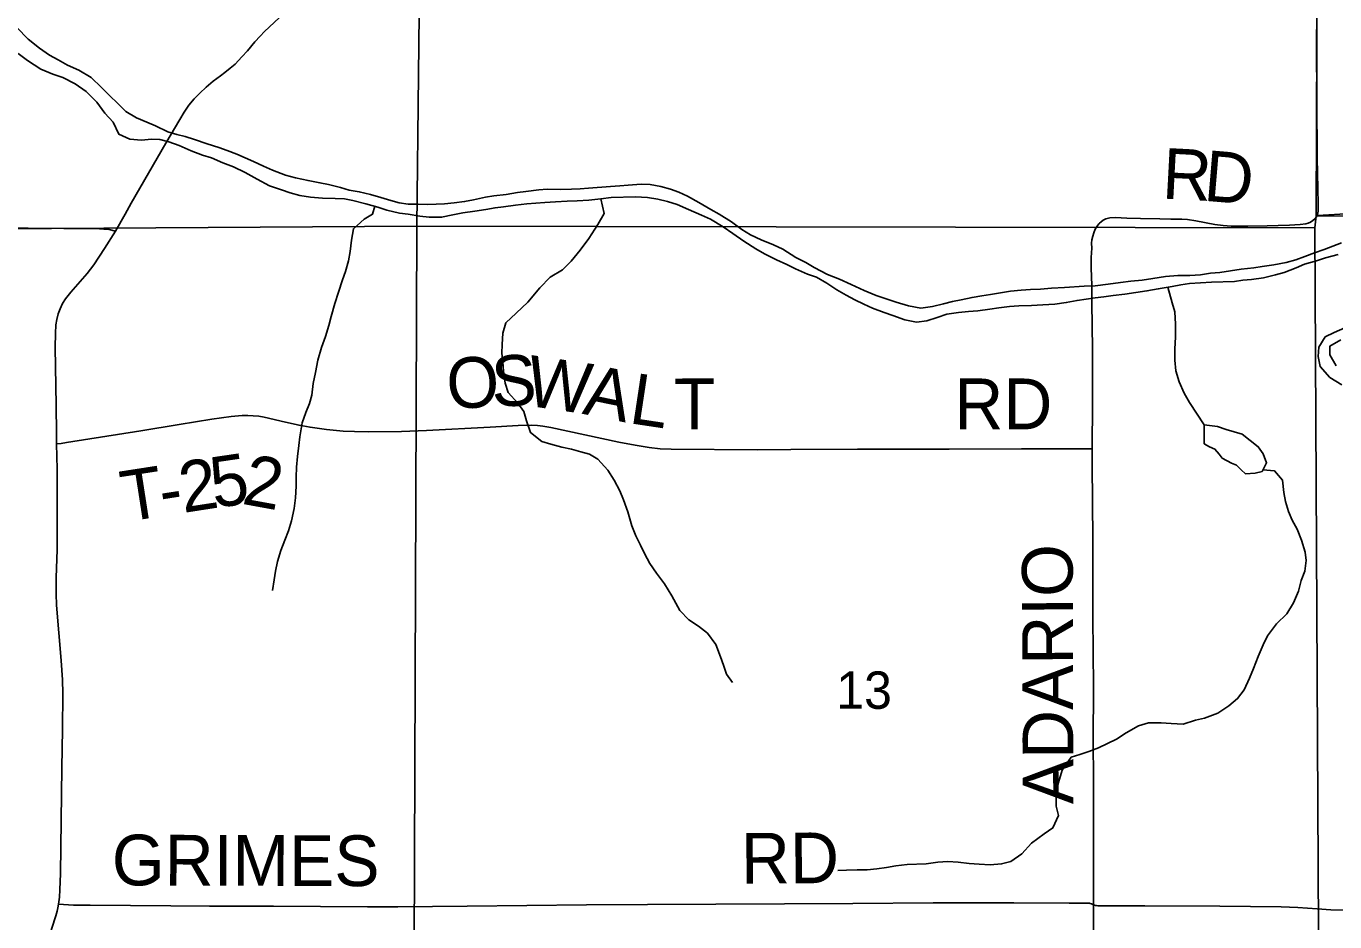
# Model space of a CAD drawing. Extents: x 0 to 34, y 0 to 22.
# Drawn here: x 3.99 to 5.455, y 15.494 to 16.497 of the extents above; entities that cross this region are included whole.
import ezdxf

# ---------------------------------------------------------------- set-up
doc = ezdxf.new("R2010")
doc.units = 0
for name, color, linetype in [('GM_X_County_Road', 7, 'Continuous'), ('GM_X_Major_River', 7, 'Continuous'), ('GM_X_Minor_Lake', 7, 'Continuous'), ('GM_X_Minor_River', 7, 'Continuous'), ('GM_X_Section', 7, 'Continuous'), ('GM_X_Section_Text', 7, 'Continuous'), ('GM_X_Township_Road', 7, 'Continuous'), ('GM_X_Township_Road_Text', 7, 'Continuous')]:
    doc.layers.add(name, color=color, linetype=linetype)

msp = doc.modelspace()

# ---------------------------------------------------------------- linework, layer by layer
at = {"layer": 'GM_X_County_Road'}
msp.add_line((4.0899, 16.2671), (4.1007, 16.2863), dxfattribs=at)
for points in [[(4.2123, 16.4449), (4.2184, 16.4497), (4.2239, 16.4544), (4.2313, 16.4623), (4.2376, 16.4693), (4.2459, 16.4793), (4.2518, 16.4857), (4.2568, 16.4907), (4.2788, 16.5115)], [(4.1007, 16.2863), (4.1075, 16.2985), (4.1463, 16.3659), (4.1621, 16.3924), (4.1669, 16.4006), (4.1722, 16.4083), (4.1782, 16.4154), (4.1845, 16.4219), (4.1914, 16.4286), (4.1992, 16.4352), (4.2076, 16.4412), (4.2123, 16.4449)], [(4.024, 16.0289), (4.0238, 16.0409), (4.0235, 16.072), (4.0225, 16.1372), (4.0227, 16.1528), (4.0233, 16.1622), (4.0243, 16.1684), (4.0258, 16.1745), (4.0279, 16.1804), (4.0307, 16.1861), (4.0341, 16.1914), (4.0398, 16.1988), (4.0583, 16.2199), (4.0657, 16.2297), (4.0778, 16.2477), (4.0899, 16.2671)], [(4.0262, 15.5135), (4.0272, 15.5213), (4.0277, 15.5296), (4.0283, 15.548), (4.0298, 15.6661), (4.0308, 15.7092), (4.0311, 15.7494), (4.0307, 15.7649), (4.0291, 15.7865), (4.024, 15.8485), (4.0235, 15.8609), (4.0237, 15.8795), (4.0246, 15.9105), (4.0248, 15.9415), (4.0245, 16.0005), (4.024, 16.0289)], [(4.0146, 15.4558), (4.0141, 15.4589), (4.0139, 15.462), (4.0139, 15.4652), (4.0141, 15.4684), (4.0145, 15.4715), (4.0159, 15.4777), (4.0187, 15.4867), (4.0233, 15.5003), (4.0246, 15.5056), (4.0255, 15.5094), (4.0262, 15.5135)]]:
    msp.add_lwpolyline(points, dxfattribs=at)
at = {"layer": 'GM_X_Major_River'}
for points in [[(4.1017, 16.4011), (4.0742, 16.428), (4.0629, 16.4395), (4.0489, 16.4475), (4.0364, 16.4533), (4.0258, 16.459), (4.0159, 16.4644), (4.005, 16.472), (3.9921, 16.4823), (3.9797, 16.4953)], [(3.9811, 16.4661), (3.9913, 16.4584), (4.0064, 16.4485), (4.02, 16.4431), (4.031, 16.4392), (4.045, 16.4323), (4.0571, 16.4236), (4.0692, 16.4117), (4.0782, 16.3992)], [(4.0782, 16.3992), (4.0873, 16.3894), (4.0938, 16.3757), (4.1059, 16.3704), (4.1192, 16.3693), (4.1302, 16.3704), (4.1396, 16.3697), (4.1495, 16.3674), (4.1612, 16.3632), (4.1745, 16.3571), (4.1874, 16.3522), (4.1976, 16.3492), (4.2101, 16.3439), (4.2219, 16.3393), (4.2351, 16.3329), (4.2484, 16.3253), (4.2624, 16.3181), (4.2757, 16.3135), (4.2855, 16.3101), (4.2962, 16.3071), (4.3083, 16.3052), (4.3219, 16.3041), (4.336, 16.3037), (4.3462, 16.3033), (4.3557, 16.3014), (4.3701, 16.298), (4.3837, 16.2942), (4.3939, 16.2908), (4.408, 16.2874), (4.4175, 16.2863), (4.4307, 16.284), (4.4413, 16.2828), (4.455, 16.2828), (4.4675, 16.2855), (4.4789, 16.2878), (4.4921, 16.2897), (4.5046, 16.2916), (4.5149, 16.2935), (4.5244, 16.2946), (4.5376, 16.2965), (4.5505, 16.298), (4.5604, 16.2984), (4.5706, 16.2992), (4.5827, 16.2999), (4.5956, 16.3007), (4.607, 16.3011), (4.6199, 16.3018), (4.6332, 16.3033), (4.6449, 16.3049), (4.6722, 16.3056), (4.6855, 16.3049), (4.6972, 16.303), (4.7078, 16.3003), (4.7188, 16.2969), (4.7313, 16.2916), (4.7461, 16.2852), (4.756, 16.2806), (4.7704, 16.2719), (4.781, 16.2647), (4.7935, 16.256), (4.8067, 16.2476), (4.8166, 16.2419), (4.8299, 16.2351), (4.8416, 16.2298), (4.8511, 16.2249), (4.8647, 16.2192), (4.8746, 16.2158), (4.8863, 16.2089), (4.8977, 16.2017), (4.9079, 16.1957), (4.9178, 16.1904), (4.9276, 16.1854), (4.9375, 16.1809), (4.9504, 16.1763), (4.9602, 16.1729), (4.9735, 16.168), (4.9868, 16.1653), (4.9981, 16.1668), (5.0099, 16.1706), (5.0205, 16.1741), (5.0338, 16.176), (5.0448, 16.1771), (5.0554, 16.1779), (5.0687, 16.1798), (5.0789, 16.1813), (5.091, 16.1828), (5.1013, 16.1835), (5.1153, 16.1839), (5.1282, 16.1847), (5.1414, 16.1854), (5.1543, 16.1873), (5.1665, 16.1896), (5.1767, 16.1911), (5.1866, 16.1927), (5.1964, 16.1938), (5.207, 16.1953), (5.2199, 16.1968), (5.2324, 16.1984), (5.2446, 16.2003), (5.2574, 16.2025), (5.273, 16.2052)], [(5.2927, 16.2177), (5.2791, 16.2177), (5.2654, 16.2166), (5.2514, 16.2143), (5.2393, 16.2124), (5.2267, 16.2113), (5.215, 16.2097), (5.2013, 16.2078), (5.1869, 16.2059), (5.1744, 16.2056), (5.1524, 16.204), (5.138, 16.2033), (5.1255, 16.2021), (5.1145, 16.2018), (5.1039, 16.201), (5.0918, 16.1999), (5.0808, 16.1983), (5.0694, 16.1964), (5.0599, 16.1949), (5.0489, 16.193), (5.0368, 16.1904), (5.027, 16.1885), (5.0171, 16.1858), (5.0046, 16.1828), (4.9917, 16.1809), (4.9777, 16.1835), (4.964, 16.1877), (4.9515, 16.1919), (4.9417, 16.1953), (4.928, 16.2006), (4.9136, 16.2074), (4.9004, 16.2135), (4.8871, 16.2188), (4.8723, 16.2264), (4.8628, 16.2321), (4.8515, 16.2378), (4.8371, 16.2469), (4.8268, 16.2518), (4.8128, 16.2575), (4.8007, 16.2632), (4.7912, 16.2689), (4.7795, 16.2776), (4.7658, 16.2863), (4.7563, 16.2916), (4.7431, 16.2992), (4.7302, 16.3064), (4.7207, 16.3109), (4.7112, 16.3144), (4.7006, 16.3174), (4.6885, 16.3193), (4.6783, 16.3197), (4.6639, 16.3189), (4.6544, 16.3181), (4.6442, 16.3174), (4.6195, 16.3155), (4.61, 16.3147), (4.6006, 16.3143), (4.5884, 16.314), (4.5733, 16.3143), (4.5638, 16.3136), (4.5494, 16.3117), (4.5399, 16.3105), (4.5274, 16.3083), (4.5137, 16.3067), (4.5043, 16.3052), (4.4906, 16.3022), (4.4808, 16.3003), (4.469, 16.2988), (4.4584, 16.298), (4.4489, 16.2973), (4.4391, 16.2969), (4.4288, 16.2973), (4.4178, 16.2976), (4.4076, 16.2991), (4.3981, 16.3014), (4.3871, 16.3048), (4.3754, 16.3082), (4.3629, 16.3113), (4.3515, 16.3132), (4.342, 16.3162), (4.3284, 16.3196), (4.3189, 16.3215), (4.3056, 16.3238), (4.2916, 16.3268), (4.2802, 16.3299), (4.2658, 16.3355), (4.2556, 16.3401), (4.2446, 16.3454), (4.2351, 16.3492), (4.2257, 16.3534), (4.2151, 16.3575), (4.2056, 16.3609), (4.1927, 16.3651), (4.1783, 16.3697), (4.1681, 16.3731), (4.1586, 16.3754), (4.1487, 16.3784), (4.1347, 16.3852), (4.1249, 16.3894), (4.1135, 16.3943), (4.1017, 16.4011)], [(5.4626, 16.2541), (5.4527, 16.2503), (5.4432, 16.2466), (5.4322, 16.2428), (5.4216, 16.239), (5.4114, 16.2352), (5.4004, 16.2321), (5.3867, 16.2295), (5.3738, 16.2276), (5.3644, 16.2261), (5.3503, 16.2245), (5.3264, 16.2211), (5.3158, 16.22), (5.3045, 16.2185), (5.2927, 16.2177)], [(5.273, 16.2052), (5.2828, 16.2071), (5.2923, 16.2086), (5.3048, 16.2094), (5.317, 16.2101), (5.3427, 16.2109), (5.3522, 16.2124), (5.3617, 16.2132), (5.3753, 16.2151), (5.3886, 16.2185), (5.3985, 16.2211), (5.4117, 16.2261), (5.4212, 16.2302), (5.4345, 16.234), (5.4447, 16.2375), (5.4588, 16.2412)], [(5.4663, 16.1589), (5.4542, 16.1536), (5.4443, 16.1487), (5.4371, 16.1373), (5.4363, 16.1267), (5.4386, 16.1157), (5.4496, 16.1032), (5.4629, 16.0952)], [(5.4564, 16.1165), (5.4496, 16.1286), (5.4496, 16.1385), (5.4617, 16.1457)]]:
    msp.add_lwpolyline(points, dxfattribs=at)
at = {"layer": 'GM_X_Minor_Lake'}
for points in [[(5.3087, 16.029), (5.3147, 16.0256), (5.3207, 16.0232), (5.3256, 16.0175), (5.329, 16.0129), (5.3395, 16.0075), (5.3448, 16.0052), (5.3501, 15.9998), (5.355, 15.9956), (5.366, 15.9963), (5.3736, 15.9981), (5.3786, 16.0079), (5.3749, 16.0178), (5.3693, 16.0258), (5.3602, 16.0327), (5.3512, 16.04), (5.3335, 16.0451), (5.3236, 16.0486), (5.3089, 16.0503)], [(5.3089, 16.0503), (5.3087, 16.029)]]:
    msp.add_lwpolyline(points, dxfattribs=at)
at = {"layer": 'GM_X_Minor_River'}
for points in [[(4.3804, 16.2951), (4.3776, 16.2862), (4.3682, 16.2806), (4.3564, 16.2699), (4.3541, 16.257), (4.3526, 16.2445), (4.3507, 16.2339), (4.3473, 16.2221), (4.3442, 16.2127), (4.3397, 16.199), (4.3355, 16.1861), (4.3313, 16.1717), (4.3287, 16.1614), (4.3249, 16.1493), (4.3207, 16.1368), (4.3165, 16.1228), (4.3139, 16.1091), (4.3112, 16.0966), (4.3097, 16.0837), (4.307, 16.0742), (4.3032, 16.0643), (4.2991, 16.0526), (4.2964, 16.037), (4.2953, 16.0272), (4.2937, 16.0147), (4.2926, 16.0029), (4.2922, 15.9919), (4.2922, 15.9817), (4.2914, 15.9684), (4.2899, 15.9566), (4.2869, 15.943), (4.2838, 15.9316), (4.2797, 15.921), (4.2751, 15.9096), (4.2713, 15.8971), (4.269, 15.8864), (4.2675, 15.8766), (4.2656, 15.8648)], [(4.6334, 16.3034), (4.6369, 16.287), (4.6301, 16.2745), (4.6199, 16.259), (4.61, 16.2461), (4.6001, 16.2336), (4.5903, 16.2241), (4.5766, 16.2157), (4.5652, 16.2036), (4.5516, 16.1876), (4.5387, 16.1755), (4.5269, 16.1645), (4.5235, 16.1531), (4.5228, 16.1402), (4.5224, 16.1307), (4.5235, 16.1209), (4.5243, 16.1106), (4.5261, 16.097), (4.5296, 16.0864), (4.5405, 16.0746), (4.547, 16.0651), (4.55, 16.0549), (4.5546, 16.0416), (4.5674, 16.0318), (4.5773, 16.0287), (4.5898, 16.0253), (4.6004, 16.023), (4.611, 16.02), (4.6205, 16.0174), (4.63, 16.012), (4.6413, 15.9995), (4.6482, 15.9885), (4.6546, 15.9764), (4.6588, 15.9665), (4.6637, 15.9529), (4.6682, 15.9373), (4.6724, 15.9259), (4.6777, 15.9157), (4.6822, 15.9062), (4.6883, 15.8952), (4.6955, 15.8842), (4.7046, 15.8721), (4.7129, 15.8588), (4.7216, 15.8425), (4.7319, 15.8319), (4.7425, 15.8247), (4.7527, 15.8171), (4.7622, 15.8042), (4.7671, 15.7905), (4.7705, 15.7811), (4.7739, 15.7712), (4.7807, 15.7617)], [(5.2682, 16.2044), (5.273, 16.1868), (5.276, 16.1769), (5.2766, 16.1629), (5.2765, 16.1488), (5.2759, 16.1352), (5.2758, 16.1227), (5.2772, 16.1109), (5.2809, 16.0983), (5.2865, 16.0858), (5.2924, 16.0755), (5.3089, 16.0503)], [(5.3745, 15.9999), (5.3876, 15.9987), (5.3966, 15.9884), (5.398, 15.9744), (5.3998, 15.9645), (5.4031, 15.9531), (5.4072, 15.9436), (5.4127, 15.9333), (5.4179, 15.9211), (5.422, 15.9078), (5.423, 15.8983), (5.4214, 15.8865), (5.4175, 15.8759), (5.4143, 15.8642), (5.4089, 15.851), (5.4012, 15.8385), (5.3897, 15.8273), (5.3797, 15.8141), (5.3747, 15.8039), (5.3693, 15.791), (5.3638, 15.7774), (5.3596, 15.7668), (5.3534, 15.7536), (5.3461, 15.7438), (5.3365, 15.7356), (5.3239, 15.7273), (5.3091, 15.7218), (5.2992, 15.7196), (5.2851, 15.7152), (5.2719, 15.7157), (5.2605, 15.7165), (5.2465, 15.7167), (5.2351, 15.7133), (5.2213, 15.7055), (5.2107, 15.6984), (5.2007, 15.6936), (5.1905, 15.6887), (5.1798, 15.6846), (5.1695, 15.6813), (5.16, 15.678), (5.1497, 15.6637), (5.1457, 15.6497), (5.143, 15.6379), (5.1432, 15.6231), (5.1457, 15.6129), (5.1395, 15.5989), (5.1296, 15.5922), (5.1155, 15.582), (5.1048, 15.57), (5.0922, 15.5614), (5.0819, 15.5585), (5.069, 15.5574), (5.0569, 15.5583), (5.0455, 15.5592), (5.0334, 15.5604), (5.0216, 15.5613), (5.0106, 15.5606), (4.9974, 15.5585), (4.9761, 15.5579), (4.9636, 15.5565), (4.9533, 15.5547), (4.9423, 15.5529), (4.9313, 15.5519), (4.9203, 15.552), (4.9082, 15.5517), (4.8987, 15.5514)]]:
    msp.add_lwpolyline(points, dxfattribs=at)
at = {"layer": 'GM_X_Section'}
for points in [[(3.4308, 17.2748), (4.4385, 17.29), (4.4273, 16.2727), (3.434, 16.2663)], [(4.4385, 17.29), (5.4379, 17.2873), (5.4343, 16.2844), (5.4328, 16.2708), (4.4273, 16.2727)], [(5.4379, 17.2873), (6.4911, 17.2929), (6.4897, 16.2833), (5.4343, 16.2844)], [(5.4343, 16.2844), (6.4897, 16.2833), (6.4927, 15.2726), (5.4377, 15.2688), (5.4328, 16.2708)], [(3.434, 16.2663), (4.4273, 16.2727), (4.4235, 15.2608), (3.4219, 15.2567), (3.4363, 15.7808)], [(4.4273, 16.2727), (5.4328, 16.2708), (5.4377, 15.2688), (5.4377, 15.257), (4.4235, 15.2608)]]:
    msp.add_lwpolyline(points, close=True, dxfattribs=at)
at = {"layer": 'GM_X_Township_Road'}
for p, q in [((5.1829, 16.2068), (5.1824, 16.2256)), ((5.1831, 16.1869), (5.1829, 16.2068))]:
    msp.add_line(p, q, dxfattribs=at)
for points in [[(5.4352, 16.2849), (5.4358, 16.286), (5.4364, 16.2897), (5.4364, 16.293), (5.4363, 16.2978), (5.4354, 16.3495), (5.4346, 16.4769), (5.4352, 16.5422), (5.437, 16.6383), (5.4372, 16.6878), (5.437, 16.7251), (5.4373, 16.7779), (5.4373, 16.7868)], [(5.1824, 16.2256), (5.1823, 16.2315), (5.1823, 16.2376), (5.1829, 16.2483), (5.1828, 16.2536), (5.1831, 16.2574), (5.1841, 16.2615), (5.1853, 16.2655), (5.1867, 16.2693), (5.1889, 16.273), (5.1909, 16.2754), (5.1917, 16.2761), (5.1934, 16.2777), (5.1957, 16.2795), (5.1988, 16.281), (5.2031, 16.2821), (5.2096, 16.2824), (5.222, 16.2817), (5.2375, 16.2814), (5.2593, 16.2812), (5.2716, 16.2808), (5.2747, 16.2806), (5.2839, 16.2808), (5.2902, 16.2803), (5.2994, 16.2789), (5.3208, 16.2747), (5.3299, 16.2735), (5.3391, 16.2728), (5.3576, 16.2727), (5.3793, 16.2733), (5.3917, 16.2735), (5.4041, 16.2738), (5.4164, 16.2746), (5.4224, 16.2754), (5.4251, 16.2761), (5.4278, 16.2774), (5.4303, 16.279), (5.4325, 16.281), (5.4344, 16.2833), (5.4352, 16.2849)], [(5.4352, 16.2849), (5.4482, 16.2855), (5.4606, 16.2861), (5.5103, 16.2873), (5.5444, 16.2879), (5.6033, 16.288), (5.6934, 16.2876), (5.7462, 16.2876), (5.7927, 16.2872), (5.8672, 16.2871), (5.9324, 16.2865), (6.01, 16.2861), (6.0784, 16.2862), (6.159, 16.2869), (6.1699, 16.2869)], [(3.4337, 16.2684), (3.4438, 16.2685), (3.5215, 16.269), (3.5584, 16.2694), (3.5894, 16.2695), (3.632, 16.2701), (3.6877, 16.2702), (3.7374, 16.2704), (3.7746, 16.2707), (3.8897, 16.2711), (3.9302, 16.2713), (3.965, 16.2709), (3.9923, 16.2705), (4.072, 16.2697), (4.077, 16.2696), (4.0828, 16.2691), (4.0899, 16.2671)], [(5.1834, 16.0233), (5.1834, 16.0275), (5.1837, 16.0704), (5.1836, 16.1105), (5.1836, 16.1353), (5.1831, 16.1869)], [(4.024, 16.0289), (4.0291, 16.0296), (4.0352, 16.0305), (4.1182, 16.0435), (4.1612, 16.0506), (4.198, 16.0565), (4.2195, 16.0595), (4.2318, 16.0606), (4.238, 16.0608), (4.2441, 16.0605), (4.2503, 16.0599), (4.2563, 16.0589), (4.2803, 16.0533), (4.2955, 16.0498), (4.3078, 16.0477), (4.3263, 16.0452), (4.3449, 16.0434), (4.3574, 16.0427), (4.3729, 16.0425), (4.4102, 16.043), (4.4381, 16.0439), (4.5096, 16.0478), (4.5407, 16.0496), (4.5561, 16.0499), (4.5623, 16.0496), (4.5684, 16.0488), (4.5775, 16.0472), (4.6536, 16.031), (4.6719, 16.0274), (4.6873, 16.0249), (4.6997, 16.0236), (4.7122, 16.023), (4.8087, 16.0224), (4.846, 16.0227), (4.9206, 16.023), (5.0233, 16.0232), (5.1042, 16.0233), (5.1757, 16.0233), (5.1834, 16.0233)], [(5.1849, 15.5129), (5.1847, 15.5179), (5.1847, 15.5583), (5.1848, 15.6547), (5.1846, 15.6951), (5.1847, 15.7572), (5.1842, 15.8349), (5.1842, 15.9219), (5.1835, 16.0058), (5.1834, 16.0233)], [(4.0262, 15.5135), (4.0431, 15.5124), (4.0617, 15.5124), (4.1518, 15.5118), (4.1953, 15.5114), (4.2667, 15.5111), (4.3722, 15.5106), (4.4061, 15.5105), (4.4837, 15.5111), (4.6172, 15.5126), (4.6856, 15.5131), (4.9154, 15.5144), (5.0055, 15.515), (5.0957, 15.515), (5.1578, 15.5147), (5.178, 15.5147), (5.1793, 15.5147), (5.1804, 15.5146), (5.1812, 15.5144), (5.1827, 15.514), (5.1849, 15.5129), (5.1871, 15.5122), (5.1882, 15.5119), (5.1896, 15.5118), (5.1907, 15.5116), (5.2424, 15.5115), (5.3264, 15.5114), (5.3949, 15.5107), (5.4135, 15.5099), (5.4353, 15.5083), (5.4507, 15.5072), (5.4662, 15.5067)], [(5.2113, 14.7556), (5.2114, 14.7637), (5.212, 14.8227), (5.2126, 14.8942), (5.2128, 14.9439), (5.2125, 14.9905), (5.2122, 15.0651), (5.2122, 15.1428), (5.2126, 15.2143), (5.2124, 15.2298), (5.2119, 15.2434), (5.2113, 15.2482), (5.211, 15.2515), (5.2094, 15.2597), (5.2087, 15.263), (5.1948, 15.3198), (5.1899, 15.341), (5.1875, 15.3533), (5.1862, 15.3626), (5.1853, 15.375), (5.1848, 15.3937), (5.1849, 15.5129)]]:
    msp.add_lwpolyline(points, dxfattribs=at)

# ---------------------------------------------------------------- texts
at = {"layer": 'GM_X_Section_Text'}
msp.add_text('13', height=0.04186, rotation=0, dxfattribs=at).set_placement((4.8969, 15.7323))
at = {"layer": 'GM_X_Township_Road_Text'}
for s, height, rotation, p in [('R', 0.0568, 357.0168, (5.2609, 16.3038)), ('D', 0.0568, 355.2297, (5.3071, 16.3014)), ('O', 0.0568, 3.0469, (4.4619, 16.0679)), ('S', 0.0568, 2.3193, (4.5117, 16.0706)), ('W', 0.0568, 351.693, (4.5472, 16.0723)), ('A', 0.0568, 348.5329, (4.6115, 16.0629)), ('L', 0.0568, 351.4206, (4.6636, 16.0524)), ('T', 0.0568, 0.1064, (4.715, 16.0454)), ('RD', 0.05682, 0, (5.029, 16.0454)), ('5', 0.0568, 8.3244, (4.2003, 15.9569)), ('2', 0.0568, 349.6556, (4.2301, 15.9621)), ('T', 0.0568, 8.8289, (4.1008, 15.9415)), ('2', 0.0568, 8.7984, (4.1658, 15.9516)), ('-', 0.0568, 8.8168, (4.1428, 15.948)), ('ADARIO', 0.05682, 90.1709, (5.1624, 15.6255)), ('GRIMES', 0.05682, 359.8174, (4.0858, 15.5346)), ('RD', 0.05682, 0.4937, (4.7904, 15.5363))]:
    msp.add_text(s, height=height, rotation=rotation, dxfattribs=at).set_placement(p)

doc.saveas('drawing.dxf')
